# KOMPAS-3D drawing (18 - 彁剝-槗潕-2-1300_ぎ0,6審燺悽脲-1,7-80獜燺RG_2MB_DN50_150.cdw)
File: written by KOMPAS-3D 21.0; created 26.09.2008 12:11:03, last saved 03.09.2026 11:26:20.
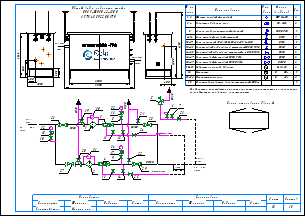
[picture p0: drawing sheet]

Sheets 1-2: A3, landscape

Document properties: Наименование: Макро:21; Автор: RaskoAdmin; Форматы листов документа: 2xA3; Полное имя файла: \\UR38nt01\Departments\КТО\КБ ПУРДГ\Заявки\Прайс-лист на типовые шкафы ГРПШ\ПРДГ_стандарт_20_03_2026\ПРДГ с RG_2MB\ПРДГ-ШУЭО-2-1300_до0,6МПа_Рвых-1,7-80кПа_RG_2MB_DN50_150.cdw

Title block, sheet 1: Наименование: Пункт учета газа / ПУГ-Ш-400-Р / ЛГТИ.485922.001ТУ; designation: ЛГТИ.03.4411141; sheet number: 1; Количество листов документа: 2; organisation: ООО "ЭЛЬСТЕР Газэлектроника"; Форматы листов документа: A3; stored path: C:\Рабочие документы\Компас\ПУГ\Схема.cdw; Разработал: Устинов; Проверил: Кошкин; Утвердил: Кошкин
Title block, sheet 2: sheet number: 2; stored path: D:\Рабочие документы\Заявки\ПУРДГ\ПУРДГ-ШУЭО-2-100-Р 4411220.cdw; designation, second copy: ЛГТИ.03.4411141-

Views: Вид 1, Вид 2
Referenced files: wcvoit.frw
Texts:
  Normal
  Вход
  газа
  PDI
  Выход
  Р=     кПа
  DN150
  DN50
  DN20
  Импульс DN20
  ≥5DN
  HYSWLongFangSong
  № на
  схеме
  Усл.
  обозн.
  Марка
  (модель)
  Кол.
  Фильтр газовый фланцевый
  ФГ 16-50
  Регулятор давления газа
  RG/2MB
  Клапан предохранительный сбросной
  КПС DN20
  Кран шаровой газовый латунный
  DN15
  Кран кнопочный VE-РАСКО-НЗ-1,6-G1/2-М20
  Кран шаровой "под приварку" штуцерный DN20 PN16
  Кран шаровой "под приварку" штуцерный п/п DN20 PN16
  Кран шаровой фланцевый DN50 PN16
  Кран шаровой фланцевый DN150 PN16
  Индикатор перепада давления
  Delta 15
  Манометр
  Манометр-напоромер
  Электрообогреватель взрывозащищенный 400Вт
  0...     МПа
  0...     кПа
  Общий вид и габариты шкафа
  ПРДГ-ШУЭО-2-1300
  Выход газа
  Вход газа
  Р=        МПа
  logo-rasko-ge.png
  Схема открывания дверей
  Предприятие изготовитель может заменять комплектующие на аналогичные,
  не ухудшающие заявленных характеристик.
  Должность
  Конструктор
  Фамилия
  Подпись
  Дата
  Согласовано
  Максимкин
  Лист
  Листов
  POLYLINE_STYLE_0.18_RGB_0_0_0
  POLYLINE_STYLE_0.50_RGB_0_0_0
  POLYLINE_STYLE_0.34_RGB_0_0_0
  PHANTOM_RGB_0_0_0_SC_1_THICK_0.18
  K5LT_THIN_RGB_0_0_0_THICK_0.18
  K5LT32769_RGB_0_0_0_THICK_0.18
  K5LT12_RGB_0_0_0_SC_1_THICK_0.18
  K5LT_DASHED_RGB_0_0_0_SC_1_THICK_0.18
  ACISOTGL_RGB_0_0_0_SC_0.8_THICK_0.25
  CONTINUOUS_RGB_0_127_31_THICK_0.3
  CONTINUOUS_RGB_0_0_255_THICK_0.35
  CONTINUOUS_RGB_255_0_0_THICK_0.35
  POLYLINE_STYLE_0.25_RGB_0_0_0
  CONTINUOUS_RGB_0_0_0_THICK_0.5
  POLYLINE_STYLE_0.35_RGB_0_0_255
  CONTINUOUS_RGB_0_0_0_THICK_0.4
  CONTINUOUS_RGB_0_0_0_THICK_0.35
  Без оформления
Dimensions and other numbers on the sheet: 1; 2; 3; 4; 5; 10; 27; 28; 29; 23; 8; 12; 19; 20; 21; 22; 25; 24; 30; 31; 15; 16; 26; 6; 7; 11; 14; 13; 33; 1, 2; 3, 4; 6-14; 9; 15-17; 18-23; 24-25; 26-27; 28-29; 30-31; 32; 33-34; 35; 400; 1050; 500; 305; 2500; 1565; 2800; 17; 34; 1000; 4130; 18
